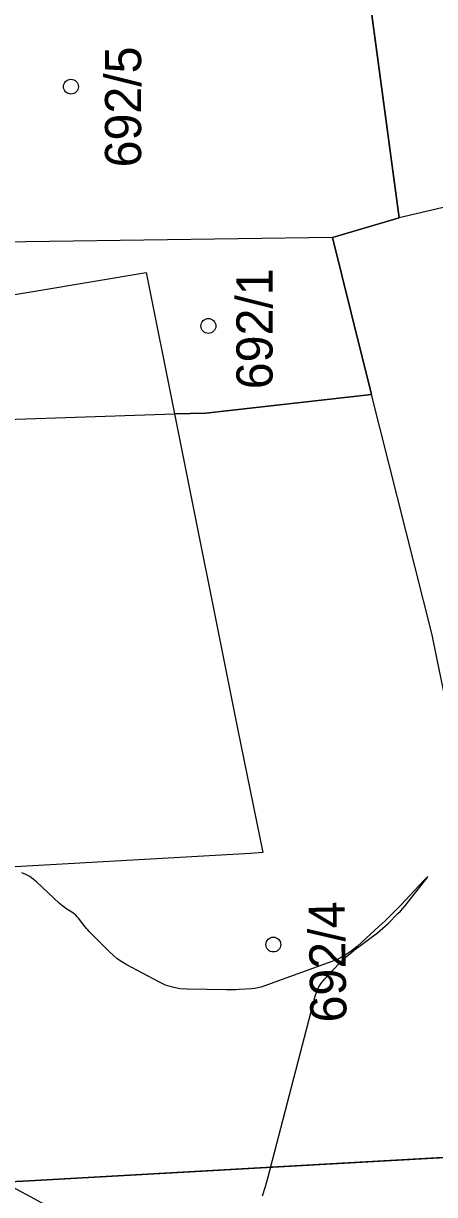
# Model space of a CAD drawing. Extents: x -534481 to -534262, y -1190577 to -1190138.
# Drawn here: x -534384.66 to -534375, y -1190505.1 to -1190477.55 of the extents above; entities that cross this region are included whole.
import ezdxf

# ---------------------------------------------------------------- set-up
doc = ezdxf.new("R2010")
doc.units = 0
for name, color, linetype in [('Definiční body', 7, 'Continuous'), ('Polygon budovy', 7, 'Continuous'), ('Polygon parcely', 7, 'Continuous'), ('Vrstva 18', 7, 'Continuous'), ('Vrstva 46', 7, 'Continuous')]:
    doc.layers.add(name, color=color, linetype=linetype)

msp = doc.modelspace()

# ---------------------------------------------------------------- linework, layer by layer
at = {"layer": 'Definiční body'}
for p, q in [((-534376.75, -1190475.31), (-534375.83, -1190482.13)), ((-534375.83, -1190482.13), (-534377.4, -1190482.59)), ((-534375.06, -1190491.94), (-534376.48, -1190486.28)), ((-534374.94, -1190492.52), (-534375.06, -1190491.94)), ((-534372.8, -1190504.12), (-534384.53, -1190504.78)), ((-534384.53, -1190504.78), (-534385.13, -1190504.81))]:
    msp.add_line(p, q, dxfattribs=at)
for points in [[(-534363.23, -1190479.17), (-534368.22, -1190480.34), (-534375.83, -1190482.13)], [(-534377.4, -1190482.59), (-534388.49, -1190482.75), (-534393.25, -1190482.82)], [(-534377.4, -1190482.59), (-534376.96, -1190484.36), (-534376.48, -1190486.28)], [(-534387.18, -1190486.94), (-534381.11, -1190486.74), (-534380.38, -1190486.72), (-534376.48, -1190486.28)], [(-534385.13, -1190504.81), (-534384.49, -1190505.16), (-534382.4, -1190506.3), (-534375.507, -1190510.084)]]:
    msp.add_lwpolyline(points, dxfattribs=at)
at = {"layer": 'Polygon parcely'}
for points in [[(-534389.45, -1190477.08), (-534389.41, -1190477.39), (-534388.49, -1190482.75), (-534388.19, -1190484.49), (-534381.78, -1190483.41), (-534381.11, -1190486.74), (-534380.38, -1190486.72), (-534376.48, -1190486.28), (-534376.96, -1190484.36), (-534377.4, -1190482.59), (-534375.83, -1190482.13), (-534376.75, -1190475.31), (-534382.56, -1190476.12)], [(-534381.11, -1190486.74), (-534379.63, -1190494.14), (-534379.04, -1190497.06), (-534379.33, -1190497.08), (-534385.97, -1190497.46), (-534389.82, -1190497.69), (-534389.86, -1190498.78), (-534389.63, -1190505.06), (-534385.13, -1190504.81), (-534384.53, -1190504.78), (-534372.8, -1190504.12), (-534374.01, -1190497.07), (-534374.08, -1190496.69), (-534374.94, -1190492.52), (-534375.06, -1190491.94), (-534376.48, -1190486.28), (-534380.38, -1190486.72)]]:
    msp.add_lwpolyline(points, close=True, dxfattribs=at)
at = {"layer": 'Vrstva 18'}
msp.add_lwpolyline([(-534379.041, -1190505.138), (-534378.973, -1190504.913), (-534378.911, -1190504.687), (-534377.804, -1190500.438), (-534377.767, -1190500.326), (-534377.717, -1190500.22), (-534377.654, -1190500.121), (-534377.579, -1190500.03), (-534377.25, -1190499.678), (-534377.166, -1190499.592), (-534377.078, -1190499.51), (-534376.987, -1190499.432), (-534376.893, -1190499.358), (-534376.341, -1190498.944), (-534376.276, -1190498.893), (-534376.213, -1190498.84), (-534376.152, -1190498.785), (-534376.093, -1190498.728), (-534375.86, -1190498.495), (-534375.802, -1190498.436), (-534375.747, -1190498.375), (-534375.693, -1190498.313), (-534375.641, -1190498.249), (-534375.236, -1190497.735), (-534375.174, -1190497.654), (-534375.156, -1190497.624), (-534375.183, -1190497.646), (-534375.254, -1190497.719), (-534375.794, -1190498.293), (-534375.917, -1190498.421), (-534376.041, -1190498.546), (-534376.169, -1190498.669), (-534376.299, -1190498.789), (-534376.823, -1190499.265), (-534376.959, -1190499.376), (-534377.103, -1190499.473), (-534377.256, -1190499.555), (-534377.418, -1190499.623), (-534379.012, -1190500.202), (-534379.082, -1190500.225), (-534379.153, -1190500.242), (-534379.226, -1190500.255), (-534379.299, -1190500.263), (-534379.595, -1190500.283), (-534379.669, -1190500.287), (-534379.743, -1190500.29), (-534379.817, -1190500.291), (-534379.891, -1190500.291), (-534380.812, -1190500.276), (-534380.988, -1190500.263), (-534381.158, -1190500.229), (-534381.323, -1190500.175), (-534381.483, -1190500.101), (-534382.245, -1190499.691), (-534382.354, -1190499.627), (-534382.458, -1190499.555), (-534382.556, -1190499.476), (-534382.648, -1190499.389), (-534383.116, -1190498.915), (-534383.15, -1190498.879), (-534383.183, -1190498.842), (-534383.215, -1190498.804), (-534383.246, -1190498.765), (-534383.369, -1190498.603), (-534383.399, -1190498.567), (-534383.432, -1190498.534), (-534383.468, -1190498.503), (-534383.506, -1190498.476), (-534383.664, -1190498.372), (-534383.703, -1190498.345), (-534383.741, -1190498.317), (-534383.777, -1190498.287), (-534383.812, -1190498.256), (-534384.357, -1190497.748), (-534384.435, -1190497.682), (-534384.517, -1190497.625), (-534384.605, -1190497.576), (-534384.698, -1190497.535)], dxfattribs=at)
at = {"layer": 'Vrstva 46'}
for centre in [(-534383.548, -1190479.042), (-534380.316, -1190484.67), (-534378.789, -1190499.223)]:
    msp.add_circle(centre, 0.175, dxfattribs=at)

# ---------------------------------------------------------------- texts
at = {"layer": 'Polygon budovy'}
for s, rotation, p in [('692/5', 90, (-534381.897, -1190480.94)), ('692/1', 90, (-534378.808, -1190486.16)), ('692/4', 91, (-534377.066, -1190501.048))]:
    msp.add_text(s, height=0.85, rotation=rotation, dxfattribs=at).set_placement(p)

doc.saveas('drawing.dxf')
